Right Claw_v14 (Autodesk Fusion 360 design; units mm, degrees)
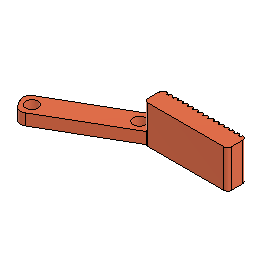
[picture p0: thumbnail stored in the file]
sketch "Sketch1" plane through (0, 0, 0) normal (0, 0, 1) x axis (1, 0, 0)
  line L1 (25, 0) -> (0, 0)
  line L2 (25, 5) -> (25, 0)
  line L3 (0, 5) -> (25, 5)
  line L4 (0, 0) -> (0, 5)
  line L5 (2.8868, 0) -> (0, 5)
  line L6 (-18.7639, -12.5) -> (2.8868, 0)
  line L7 (-21.6506, -7.5) -> (-18.7639, -12.5)
  line L8 (0, 5) -> (-21.6506, -7.5)
  line L9 (1.4434, 2.5) -> (-20.2073, -10)
  line L10 (25, 0) -> (2.8868, 0)
  line L11 (25, 5) -> (25, 0)
  line L12 (2.8868, 5) -> (25, 5)
  line L13 (2.8868, 0) -> (2.8868, 5)
  circle C1 centre (-18.0422, -8.75) radius 1.6
  circle C2 centre (0, 1.6667) radius 1.6
  point P1 (0, 0)
  point P2 (0, 0)
  point P6 (2.8868, 0)
  point P9 (-20.2073, -10)
  point P10 (1.4434, 2.5)
  point P11 (-18.0422, -8.75)
  point P12 (0, 1.6667)
  point P3 (25, 0)
  point P5 (0, 5)
  point P8 (-21.6506, -7.5)
  horizontal L1
  vertical L2
  horizontal L3
  vertical L4
  coincident P1 P2
  perpendicular L5 L6
  parallel L5 L7
  parallel L6 L8
  coincident L1 P6
  midpoint L7 P9
  midpoint L5 P10
  coincident L9 P11
  coincident L4 P12
  coincident L9 P12
  horizontal L10
  vertical L11
  horizontal L12
  vertical L13
  dimension "d1" distance P2 P3 = 25
  dimension "d2" distance P2 P5 = 5
  dimension "d3" distance P5 P8 = 25
  dimension "d4" diameter C1 = 3.2
  dimension "d5" distance L7 P11 = 2.5
  dimension "d8" angle L1 L6 = 150
  dimension "d9" diameter C2 = 3.2
extrude "Extrude1" new body sketch "Sketch1" profile of L1 L3 L4 L5 L6 L7 L8 C1 C2 L13 along normal blind 3
extrude "Extrude2" add sketch "Sketch1" profile of L1 L2 L3 L10 L11 L12 L13 along normal blind 10
sketch "Sketch3" plane through (0, 0, 0) normal (0, 0, -1) x axis (1, 0, 0)
  line L1 (25, -5) -> (0, -5)
  line L2 (-18.7639, 12.5) -> (2.8868, 0)
  line L3 (-21.6506, 7.5) -> (-18.7639, 12.5)
  line L4 (0, -5) -> (-21.6506, 7.5)
  line L5 (24, -3.4542) -> (24, -5)
  line L6 (23.2, -5) -> (24, -5)
  line L7 (23.7507, -4.5) -> (23.4493, -4.5)
  line L8 (23.7507, -4.5) -> (24, -5)
  line L9 (23.6, -5) -> (23.6, -4.5)
  line L10 (23.4493, -4.5) -> (23.2, -5)
  line L11 (22.0922, -4.5) -> (21.8429, -5)
  line L12 (22.3936, -4.5) -> (22.0922, -4.5)
  line L13 (22.3936, -4.5) -> (22.6429, -5)
  line L14 (21.8429, -5) -> (22.6429, -5)
  line L15 (20.735, -4.5) -> (20.4857, -5)
  line L16 (21.0364, -4.5) -> (20.735, -4.5)
  line L17 (21.0364, -4.5) -> (21.2857, -5)
  line L18 (20.4857, -5) -> (21.2857, -5)
  line L19 (19.3779, -4.5) -> (19.1286, -5)
  line L20 (19.6793, -4.5) -> (19.3779, -4.5)
  line L21 (19.6793, -4.5) -> (19.9286, -5)
  line L22 (19.1286, -5) -> (19.9286, -5)
  line L23 (18.0207, -4.5) -> (17.7714, -5)
  line L24 (18.3221, -4.5) -> (18.0207, -4.5)
  line L25 (18.3221, -4.5) -> (18.5714, -5)
  line L26 (17.7714, -5) -> (18.5714, -5)
  line L27 (16.6636, -4.5) -> (16.4143, -5)
  line L28 (16.965, -4.5) -> (16.6636, -4.5)
  line L29 (16.965, -4.5) -> (17.2143, -5)
  line L30 (16.4143, -5) -> (17.2143, -5)
  line L31 (15.3064, -4.5) -> (15.0571, -5)
  line L32 (15.6078, -4.5) -> (15.3064, -4.5)
  line L33 (15.6078, -4.5) -> (15.8571, -5)
  line L34 (15.0571, -5) -> (15.8571, -5)
  line L35 (13.9493, -4.5) -> (13.7, -5)
  line L36 (14.2507, -4.5) -> (13.9493, -4.5)
  line L37 (14.2507, -4.5) -> (14.5, -5)
  line L38 (13.7, -5) -> (14.5, -5)
  line L39 (12.5922, -4.5) -> (12.3429, -5)
  line L40 (12.8936, -4.5) -> (12.5922, -4.5)
  line L41 (12.8936, -4.5) -> (13.1429, -5)
  line L42 (12.3429, -5) -> (13.1429, -5)
  line L43 (11.235, -4.5) -> (10.9857, -5)
  line L44 (11.5364, -4.5) -> (11.235, -4.5)
  line L45 (11.5364, -4.5) -> (11.7857, -5)
  line L46 (10.9857, -5) -> (11.7857, -5)
  line L47 (9.8779, -4.5) -> (9.6286, -5)
  line L48 (10.1793, -4.5) -> (9.8779, -4.5)
  line L49 (10.1793, -4.5) -> (10.4286, -5)
  line L50 (9.6286, -5) -> (10.4286, -5)
  line L51 (8.5207, -4.5) -> (8.2714, -5)
  line L52 (8.8221, -4.5) -> (8.5207, -4.5)
  line L53 (8.8221, -4.5) -> (9.0714, -5)
  line L54 (8.2714, -5) -> (9.0714, -5)
  line L55 (7.1636, -4.5) -> (6.9143, -5)
  line L56 (7.465, -4.5) -> (7.1636, -4.5)
  line L57 (7.465, -4.5) -> (7.7143, -5)
  line L58 (6.9143, -5) -> (7.7143, -5)
  line L59 (5.8064, -4.5) -> (5.5571, -5)
  line L60 (6.1078, -4.5) -> (5.8064, -4.5)
  line L61 (6.1078, -4.5) -> (6.3571, -5)
  line L62 (5.5571, -5) -> (6.3571, -5)
  line L63 (4.4493, -4.5) -> (4.2, -5)
  line L64 (4.7507, -4.5) -> (4.4493, -4.5)
  line L65 (4.7507, -4.5) -> (5, -5)
  line L66 (4.2, -5) -> (5, -5)
  line L67 (25, 0) -> (25, -5)
  line L68 (2.8868, 0) -> (25, 0)
  circle C1 centre (-18.0422, 8.75) radius 1.6
  circle C2 centre (0, -1.6667) radius 1.6
  point P9 (24, -5)
  point P14 (23.6, -5)
  point P15 (23.2, -5)
  point P12 (23.7507, -4.5)
  point P16 (23.4493, -4.5)
  point P13 (23.6, -4.5)
  point P11 (23.2, -5)
  coincident L1 P9
  perpendicular L1 L5
  horizontal L6
  horizontal L7
  midpoint L6 P14
  symmetric P9 L9 P15
  symmetric P12 L9 P16
  coincident L7 P13
  dimension "d29" distance P9 P11 = 0.8
  dimension "d33" R-Pattern1-uDistance = -19
  dimension "d34" R-Pattern1-vDistance = 0
extrude "Extrude4" cut sketch "Sketch3" profile of L1 L6 L7 L8 L10 L11 L12 L13 L14 L15 L16 L17 L18 L19 L20 L21 L22 L23 L24 L25 L26 L27 L28 L29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 against normal blind 10
fillet "Fillet3" radius 2
fillet "Fillet4" radius 1
fillet "Fillet8" radius 1
fillet "Fillet9" radius 1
